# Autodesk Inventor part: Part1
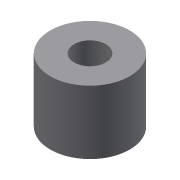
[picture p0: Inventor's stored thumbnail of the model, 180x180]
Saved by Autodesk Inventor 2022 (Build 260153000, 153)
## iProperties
Created: 2002-01
Part Number: Part1
Document SubType Name: Modeling
Designer: ***
Density: 1 g/cm^3
Material: Generic
Appearance: Default
Control State: 0
Master: False
Checked Out: False
Shininess: 77.0
Angle Display Precision: 2
Document Length Units: 11269
Document Angle Units: 11279
Document Time Units: 11290
Document Mass Units: 11283
Document Length Units Precision: 3
Document Angle Units Precision: 2
Density: 0.0
Volumn: 0.0
Area: 0.0
PropertySet Name: Model Information
Author: ***
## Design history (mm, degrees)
sketch "Sketch1"
  geometry: C1 r 25 at (0, 0); C2 r 10 at (0, 0)
  constraints: 2 centre point, 1 coincident
  dimensions: "d0" = 50 diameter of C1; "d1" = 20 diameter of C2
extrude "Extrusion1" new body sketch "Sketch1" distance "d2" = 40; taper "d3" = 0 deg
body "Solid1"
